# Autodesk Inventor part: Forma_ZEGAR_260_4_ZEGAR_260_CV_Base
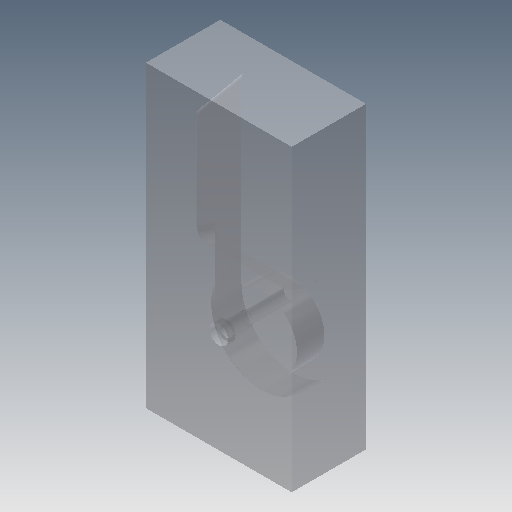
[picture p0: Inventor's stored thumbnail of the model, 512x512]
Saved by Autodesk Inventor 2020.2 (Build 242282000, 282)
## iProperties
Created: 2015-01
Part Number: Forma_ZEGAR_260_4_ZEGAR_260_CV_Base
Material: Ogólny
Document SubType Name: Modeling
Designer: F.Stasiak
Density: 1 g/cm^3
Appearance: Domyślna
Catalog Web Link: www.expertbooks.pl
Manager: www.cadconsulting.pl
Company: Fabian Stasiak CAD Consulting
Author: F.Stasiak
Subject: Zbiór ćwiczeń. Autodesk Inventor 2020. Kurs Professional
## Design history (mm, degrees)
node "Forma_ZEGAR_260_4_ZEGAR_260_MP"
sketch "Szkic1"
  geometry: 1 further point
hole "Otwór1" sketch "Szkic1" at (39, -106.407) diameter "d0" = 7; stored, may be unused: countersink angle "d4" = 90 deg, drill point angle "d6" = 118 deg; dims "d1" = 6, "d2" = 10, "d3" = 4, "d5" = 15
feature "Rzeźbienie2"
feature "Bryła4::Forma_ZEGAR_260_4_ZEGAR_260_MP"
tag "Bryła wyprowadzona1"
node "Bryła1"
feature "Forma_ZEGAR_260_4_ZEGAR_260_MP_Bodies"
feature "Powierzchnia2"
body "Srf2"
